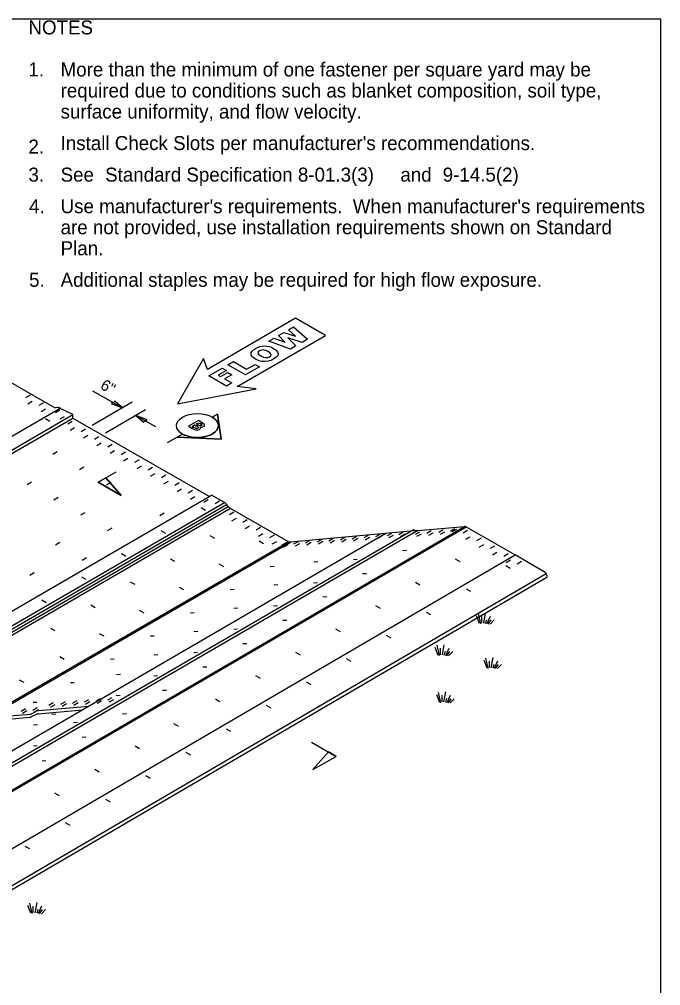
# Model space of a CAD drawing. Extents: x 99862 to 103151, y 100000 to 102076.
# Drawn here: x 102236 to 103151, y 100697 to 102076 of the extents above; entities that cross this region are included whole.
import ezdxf

# ---------------------------------------------------------------- set-up
doc = ezdxf.new("R2010")
doc.units = 0
for name, color, linetype in [('Level 1', 7, 'Continuous'), ('Level 15', 7, 'Continuous'), ('Level 20', 7, 'Continuous'), ('Level 25', 7, 'Continuous'), ('Level 31', 7, 'Continuous'), ('Level 32', 7, 'Continuous'), ('Level 33', 7, 'Continuous'), ('Level 34', 7, 'Continuous'), ('Level 36', 7, 'Continuous'), ('Level 60', 7, 'Continuous')]:
    doc.layers.add(name, color=color, linetype=linetype)

msp = doc.modelspace()

# ---------------------------------------------------------------- linework, layer by layer
at = {"layer": 'Level 1'}
msp.add_lwpolyline([(99862, 99999.5), (103151, 99999.5), (103151, 102075.5), (99862, 102075.5)], close=True, dxfattribs=at)
at = {"layer": 'Level 15'}
for p, q in [((102340.6, 101545.8), (102383.2, 101521.4)), ((102397.1, 101529.4), (102339.9, 101496.3)), ((102416.2, 101518.5), (102359, 101485.4)), ((102402.3, 101510.5), (102430.1, 101494.6))]:
    msp.add_line(p, q, dxfattribs=at)
for points in [[(102383.2, 101521.4), (102372.3, 101530.8), (102370.2, 101528.9), (102366.9, 101527.7)], [(102402.3, 101510.5), (102413.3, 101501.1), (102415.3, 101503), (102418.6, 101504.2)]]:
    msp.add_lwpolyline(points, close=True, dxfattribs=at)
at = {"layer": 'Level 20'}
for p, q in [((102447.5, 101471.9), (102468.8, 101484)), ((102348.6, 101415.4), (102374.4, 101430.2)), ((102653, 101044.5), (102688, 101024.3))]:
    msp.add_line(p, q, dxfattribs=at)
for points in [[(102547, 101551.7), (102673, 101624.4), (102630.2, 101649.1), (102504.3, 101576.3), (102498.9, 101591.7), (102461.5, 101527), (102573.7, 101548.6), (102547, 101551.7)], [(102630.4, 101609.7), (102622.8, 101605.3), (102592.1, 101616.6), (102599.5, 101620.9), (102614.9, 101615.2), (102605.8, 101624.5), (102613.6, 101629), (102629.8, 101623.8), (102619.9, 101632.7), (102627.1, 101636.8), (102646.9, 101619.2), (102639.3, 101614.8), (102619, 101621.4), (102630.4, 101609.7)], [(102586.5, 101587.4), (102581.9, 101587.7), (102579.6, 101588.1), (102577.3, 101588.8), (102575, 101589.8), (102572.8, 101590.9), (102570.1, 101592.7), (102568.2, 101594.6), (102567, 101596.5), (102566.6, 101598.5), (102567, 101600.4), (102568.2, 101602.3), (102570.1, 101604.2), (102572.8, 101606), (102575.9, 101607.6), (102579.2, 101608.7), (102582.5, 101609.4), (102585.8, 101609.6), (102589.2, 101609.4), (102592.5, 101608.8), (102595.6, 101607.7), (102598.7, 101606.1), (102602.4, 101603.6), (102604.5, 101601.1), (102605.2, 101598.6), (102604.6, 101596), (102602.6, 101593.5), (102599.2, 101591.1), (102594.9, 101589), (102590.8, 101587.8), (102586.5, 101587.4)], [(102587.5, 101593), (102590.5, 101593.3), (102593.1, 101594.3), (102595, 101595.8), (102595.4, 101597.5), (102594.1, 101599.4), (102590.9, 101601.7), (102587.4, 101603.3), (102584.1, 101603.9), (102581.2, 101603.7), (102578.5, 101602.6), (102576.8, 101601.1), (102576.4, 101599.5), (102577.6, 101597.5), (102580.6, 101595.4), (102584.2, 101593.7), (102587.5, 101593)], [(102539.1, 101557), (102531.4, 101552.5), (102506.2, 101567), (102525.6, 101578.2), (102531.4, 101574.8), (102519.8, 101568.1), (102523.1, 101566.2), (102533.3, 101572), (102539.1, 101568.7), (102528.9, 101562.8), (102539.1, 101557)], [(102578.7, 101579.8), (102558.9, 101568.4), (102533.7, 101582.9), (102541.4, 101587.4), (102560.3, 101576.5), (102572.4, 101583.4), (102578.7, 101579.8)]]:
    msp.add_lwpolyline(points, dxfattribs=at)
at = {"layer": 'Level 25'}
for p, q in [((102511.3, 101508.2), (102518.8, 101512.5)), ((102518.8, 101512.5), (102511.3, 101508.2)), ((102518.8, 101512.5), (102524.1, 101476.5)), ((102524.1, 101476.5), (102518.8, 101512.5)), ((102484.8, 101493.7), (102482.3, 101492.5)), ((102482.3, 101492.5), (102484.8, 101493.7)), ((102491.1, 101496.9), (102488.5, 101495.6)), ((102488.5, 101495.6), (102491.1, 101496.9)), ((102497.1, 101499.9), (102494.5, 101498.6)), ((102494.5, 101498.6), (102497.1, 101499.9)), ((102461.3, 101479.7), (102468.8, 101484)), ((102468.8, 101484), (102461.3, 101479.7)), ((102524.1, 101476.5), (102461.3, 101479.7)), ((102461.3, 101479.7), (102524.1, 101476.5))]:
    msp.add_line(p, q, dxfattribs=at)
for points in [[(102497.1, 101499.9), (102491.4, 101503.1), (102477.5, 101495.2), (102482.3, 101492.5)], [(102482.3, 101492.5), (102485.8, 101490.6), (102487, 101490.1), (102488.3, 101489.8), (102489.6, 101489.8), (102490.9, 101489.9), (102492.1, 101490.3), (102493.2, 101490.7), (102494.1, 101491.4), (102494.6, 101492.3), (102494.6, 101493.1), (102494.1, 101494), (102495.3, 101493.8), (102496.7, 101493.9), (102497.9, 101494.2), (102499, 101494.7), (102499.8, 101495.2), (102500.2, 101495.9), (102500.4, 101496.5), (102500.3, 101497.2), (102500, 101497.8), (102499.4, 101498.3), (102497.1, 101499.9)], [(102484.8, 101493.7), (102482.6, 101495), (102486.1, 101497), (102488.5, 101495.6), (102488.5, 101495.6)], [(102488.5, 101495.6), (102490.1, 101494.6), (102491, 101494), (102491.3, 101493.5), (102491.3, 101493.1), (102491.1, 101492.7), (102490.7, 101492.3), (102489.9, 101492), (102489.1, 101491.9), (102488.3, 101492), (102487.5, 101492.3), (102485.4, 101493.4), (102484.8, 101493.7)], [(102491.1, 101496.9), (102490.5, 101497.2), (102488.5, 101498.4), (102491.7, 101500.2), (102493.4, 101499.2), (102494.5, 101498.6)], [(102494.5, 101498.6), (102495.9, 101497.7), (102496.4, 101497.2), (102496.6, 101496.8), (102496.4, 101496.3), (102495.9, 101496), (102495.2, 101495.7), (102494.4, 101495.6), (102493.5, 101495.7), (102492.7, 101496), (102491.1, 101496.9)], [(102359.6, 101421.7), (102381.5, 101396.5), (102348.6, 101415.4), (102359.6, 101421.7)], [(102348.6, 101415.4), (102381.5, 101396.5), (102359.6, 101421.7), (102348.6, 101415.4)], [(102677.1, 101030.6), (102654.8, 101005.4), (102688, 101024.3), (102677.1, 101030.6)], [(102677.1, 101030.6), (102654.8, 101005.4), (102688, 101024.3), (102677.1, 101030.6)]]:
    msp.add_lwpolyline(points, dxfattribs=at)
msp.add_ellipse((102490.1, 101496.1), major_axis=(29.9, 0.1), ratio=0.572617, dxfattribs=at)
for start_param, end_param in [(3.920114, 7.061799), (5.490949, 7.061799), (3.920114, 5.425871), (5.425871, 5.490949)]:
    msp.add_ellipse((102490.1, 101496.1), major_axis=(29.9, 0.1), ratio=0.572617, start_param=start_param, end_param=end_param, dxfattribs=at)
at = {"layer": 'Level 31'}
for p, q in [((102892.7, 101213.7), (102888.4, 101224.7)), ((102894.3, 101213.4), (102891, 101228.1)), ((102896, 101214.6), (102896, 101223.8)), ((102898.6, 101214.3), (102901.3, 101228.8)), ((102901.3, 101214), (102902.9, 101219.5)), ((102903.3, 101213.6), (102908.1, 101224.1)), ((102904.9, 101213), (102909.1, 101218.9)), ((102907.6, 101213), (102913.5, 101219)), ((102833.7, 101168.4), (102829.3, 101179.4)), ((102835.3, 101168.1), (102832, 101182.8)), ((102837, 101169.3), (102837, 101178.5)), ((102839.6, 101169), (102842.3, 101183.5)), ((102844.3, 101168.3), (102849.1, 101178.8)), ((102842.3, 101168.8), (102843.9, 101174.2)), ((102845.9, 101167.7), (102850, 101173.7)), ((102848.5, 101167.7), (102854.5, 101173.7)), ((102904.9, 101149.8), (102901.6, 101164.5)), ((102909.2, 101150.7), (102911.9, 101165.2)), ((102903.3, 101150.1), (102899, 101161.1)), ((102906.6, 101151), (102906.6, 101160.2)), ((102911.9, 101150.4), (102913.5, 101155.9)), ((102913.9, 101150), (102918.7, 101160.5)), ((102915.5, 101149.4), (102919.7, 101155.3)), ((102918.2, 101149.4), (102924.1, 101155.4)), ((102835.8, 101101.2), (102831.5, 101112.2)), ((102837.4, 101100.9), (102834.1, 101115.6)), ((102839.1, 101102.2), (102839.1, 101111.4)), ((102841.8, 101101.9), (102844.5, 101116.4)), ((102846.5, 101101.1), (102851.3, 101111.7)), ((102844.5, 101101.6), (102846.1, 101107.1)), ((102848.1, 101100.6), (102852.2, 101106.5)), ((102850.7, 101100.6), (102856.6, 101106.6)), ((102252.6, 100800.6), (102248.3, 100811.6)), ((102254.2, 100800.3), (102250.9, 100815)), ((102255.9, 100801.5), (102255.9, 100810.7)), ((102258.6, 100801.2), (102261.3, 100815.7)), ((102261.3, 100801), (102262.9, 100806.4)), ((102263.3, 100800.5), (102268.1, 100811)), ((102264.9, 100799.9), (102269, 100805.9)), ((102267.5, 100799.9), (102273.4, 100805.9))]:
    msp.add_line(p, q, dxfattribs=at)
msp.add_lwpolyline([(102076.8, 100748.1), (102988.4, 101279.9)], dxfattribs=at)
at = {"layer": 'Level 32'}
msp.add_line((102312.5, 101506.6), (102507.3, 101395), dxfattribs=at)
at = {"layer": 'Level 33'}
for p, q in [((102758.7, 101342.1), (101851.6, 100814.7)), ((102799.4, 101348.1), (101885.5, 100817.3)), ((102804.5, 101346.3), (101890.1, 100815.2)), ((101954.5, 100818.6), (102871, 101352.2)), ((101957.1, 100818), (102873.6, 101351.6)), ((102986.2, 101286.5), (102943.4, 101311.7)), ((102988.4, 101282.7), (102988.4, 101279.9))]:
    msp.add_line(p, q, dxfattribs=at)
for points in [[(102804.5, 101346.3), (102871, 101352.2)], [(102873.6, 101351.6), (102943.4, 101311.7)], [(102030.9, 100779.4), (102943.4, 101311.7)], [(102075.3, 100752.6), (102987.8, 101284.9)]]:
    msp.add_lwpolyline(points, dxfattribs=at)
for centre, start, end in [((102871.4, 101347.7), 60.264, 95.0898), ((102983.9, 101282.7), 0, 59.4804)]:
    msp.add_arc(centre, 4.5, start, end, dxfattribs=at)
at = {"layer": 'Level 34'}
for p, q in [((102285.7, 101521.9), (102203.7, 101568.9)), ((102289.6, 101521.8), (102287.3, 101521.5)), ((102294.5, 101520.5), (101638.3, 101141.9)), ((101744.8, 101183.1), (102312.5, 101511.8)), ((102312.5, 101511.8), (102294.5, 101520.5)), ((102312.5, 101506.6), (102312.5, 101511.8)), ((101745.3, 101179), (102312.5, 101506.6)), ((102095.5, 101156.3), (102510.4, 101396.8)), ((102528.6, 101386.5), (102510.4, 101396.8)), ((102112.2, 101145.1), (102528.6, 101386.5)), ((102115.5, 101142.2), (102531.8, 101383.6)), ((102534.1, 101380.7), (102531.8, 101383.6)), ((102537.4, 101377.8), (102101.1, 101124.8)), ((102117.8, 101139.2), (102534.1, 101380.7)), ((102619.9, 101330.5), (102537.4, 101377.8)), ((102804.5, 101346.3), (102623.1, 101329.6)), ((102201.4, 101088.1), (102619.9, 101330.5)), ((102202.1, 101086.4), (102623.1, 101329.6)), ((102263.4, 101089.8), (102334.9, 101095.7)), ((102180.8, 101074), (102251.4, 101080)), ((102182.5, 101078.7), (102252, 101084.6)), ((102260.9, 101084.6), (102253.1, 101080.5)), ((102261.7, 101089.3), (102253.7, 101085.1)), ((102262.9, 101085.2), (102326.2, 101090.6))]:
    msp.add_line(p, q, dxfattribs=at)
for centre, start, end in [((102251, 101084.5), 274.8534, 297.6625), ((102251.6, 101089.1), 274.8534, 297.6625), ((102263.8, 101085.3), 94.8997, 117.6625)]:
    msp.add_arc(centre, 4.5, start, end, dxfattribs=at)
for centre, major_axis, ratio, start_param, end_param in [((102285.7, 101525.6), (2.23, -3.87), 0.581719, 5.498177, 6.032289), ((102294.5, 101509.6), (6.7, -11.6), 0.581714, 2.356435, 2.890593), ((102267.7, 101072.9), (-6.8, 11.7), 0.579285, 6.016164, 6.283108)]:
    msp.add_ellipse(centre, major_axis=major_axis, ratio=ratio, start_param=start_param, end_param=end_param, dxfattribs=at)
for points in [[(102531.8, 101383.6), (102530.8, 101384.8), (102529.7, 101385.8), (102528.6, 101386.5)], [(102537.4, 101377.8), (102536.2, 101378.4), (102535.1, 101379.4), (102534.1, 101380.7)], [(102623.1, 101329.6), (102622.1, 101329.5), (102621.1, 101329.8), (102619.9, 101330.5)]]:
    msp.add_open_spline(points, degree=3, dxfattribs=at)
at = {"layer": 'Level 36'}
for p, q in [((102251.3, 101539.4), (102245, 101535.8)), ((102251.3, 101539.4), (102245, 101535.8)), ((102254.5, 101530.3), (102248.2, 101526.7)), ((102270.3, 101528.5), (102264, 101524.9)), ((102273.5, 101519.4), (102267.2, 101515.8)), ((102294, 101518), (102287.7, 101514.4)), ((102300, 101508.8), (102293.7, 101505.1)), ((102273.2, 101506.1), (102279.6, 101502.5)), ((102311.5, 101501.9), (102305.2, 101498.3)), ((102311.5, 101501.9), (102305.2, 101498.3)), ((102311.5, 101501.9), (102305.2, 101498.3)), ((102314.7, 101492.8), (102308.4, 101489.2)), ((102314.7, 101492.8), (102308.4, 101489.2)), ((102330.6, 101491), (102324.3, 101487.3)), ((102330.6, 101491), (102324.3, 101487.3)), ((102333.8, 101481.9), (102327.5, 101478.2)), ((102333.8, 101481.9), (102327.5, 101478.2)), ((102349.6, 101480.1), (102343.3, 101476.4)), ((102349.6, 101480.1), (102343.3, 101476.4)), ((102352.8, 101471), (102346.5, 101467.3)), ((102352.8, 101471), (102346.5, 101467.3)), ((102368.7, 101469.1), (102362.4, 101465.5)), ((102368.7, 101469.1), (102362.4, 101465.5)), ((102290.1, 101458.7), (102283.8, 101455)), ((102371.9, 101460), (102365.6, 101456.4)), ((102371.9, 101460), (102365.6, 101456.4)), ((102387.7, 101458.2), (102381.4, 101454.6)), ((102387.7, 101458.2), (102381.4, 101454.6)), ((102387.7, 101458.2), (102381.4, 101454.6)), ((102391, 101449.1), (102384.7, 101445.5)), ((102391, 101449.1), (102384.7, 101445.5)), ((102406.8, 101447.3), (102400.5, 101443.6)), ((102410.1, 101438.2), (102403.8, 101434.5)), ((102328.2, 101436.8), (102321.9, 101433.2)), ((102425.9, 101436.4), (102419.6, 101432.7)), ((102429.1, 101427.2), (102422.8, 101423.6)), ((102445, 101425.4), (102438.7, 101421.8)), ((102253.4, 101415.4), (102247.1, 101411.8)), ((102366.4, 101415), (102360.1, 101411.3)), ((102448.2, 101416.3), (102441.9, 101412.7)), ((102464.1, 101414.5), (102457.8, 101410.8)), ((102467.3, 101405.4), (102461, 101401.7)), ((102483.2, 101403.5), (102476.9, 101399.9)), ((102291.5, 101393.6), (102285.2, 101389.9)), ((102486.4, 101394.4), (102480.1, 101390.8)), ((102505.6, 101390.1), (102499.3, 101386.4)), ((102521.5, 101388.3), (102515.2, 101384.6)), ((102329.7, 101371.7), (102323.4, 101368.1)), ((102442.7, 101371.2), (102436.4, 101367.6)), ((102501.8, 101375.2), (102495.4, 101378.8)), ((102524.7, 101379.1), (102518.4, 101375.5)), ((102542, 101372.6), (102535.7, 101368.9)), ((102545.2, 101363.4), (102538.9, 101359.8)), ((102561.1, 101361.6), (102554.8, 101358)), ((102561.1, 101361.6), (102554.8, 101358)), ((102367.8, 101349.8), (102361.5, 101346.2)), ((102445, 101342.3), (102438.6, 101345.9)), ((102445, 101342.3), (102438.6, 101345.9)), ((102564.4, 101352.5), (102558.1, 101348.8)), ((102580.2, 101350.6), (102573.9, 101347)), ((102583.5, 101341.5), (102577.2, 101337.8)), ((102767.2, 101342.4), (102760.9, 101338.8)), ((102783.8, 101343.9), (102777.5, 101340.2)), ((102807.1, 101344.3), (102800.8, 101340.6)), ((102823.8, 101345.8), (102817.5, 101342.1)), ((102823.8, 101345.8), (102817.5, 101342.1)), ((102825.9, 101342.8), (102819.6, 101339.2)), ((102840.6, 101347.3), (102834.3, 101343.6)), ((102842.7, 101344.3), (102836.4, 101340.7)), ((102857.4, 101348.8), (102851.1, 101345.1)), ((102859.5, 101348.1), (102853.2, 101344.5)), ((102875.4, 101346.3), (102869.1, 101342.6)), ((102293.8, 101329.2), (102287.5, 101325.6)), ((102514.7, 101335.1), (102508.3, 101338.7)), ((102584.3, 101327.4), (102578, 101331.1)), ((102599.4, 101339.7), (102593.1, 101336)), ((102602.7, 101330.5), (102596.4, 101326.9)), ((102617, 101329.1), (102610.7, 101325.4)), ((102633.7, 101330.5), (102627.4, 101326.9)), ((102650.4, 101332), (102644.1, 101328.4)), ((102652.4, 101329.1), (102646.1, 101325.4)), ((102667.1, 101333.5), (102660.8, 101329.9)), ((102667.1, 101333.5), (102660.8, 101329.9)), ((102669.1, 101330.6), (102662.8, 101326.9)), ((102683.7, 101335), (102677.4, 101331.3)), ((102685.8, 101332.1), (102679.5, 101328.4)), ((102700.4, 101336.5), (102694.1, 101332.8)), ((102702.5, 101333.6), (102696.2, 101329.9)), ((102717.1, 101338), (102710.8, 101334.3)), ((102719.1, 101335), (102712.8, 101331.4)), ((102733.8, 101339.5), (102727.5, 101335.8)), ((102733.8, 101339.5), (102727.5, 101335.8)), ((102735.8, 101336.5), (102729.5, 101332.9)), ((102750.5, 101340.9), (102744.2, 101337.3)), ((102752.5, 101338), (102746.2, 101334.4)), ((102769.2, 101339.5), (102762.9, 101335.8)), ((102785.9, 101341), (102779.6, 101337.3)), ((102809.1, 101341.3), (102802.8, 101337.7)), ((102878.8, 101337.1), (102872.5, 101333.5)), ((102894.7, 101335.3), (102888.4, 101331.6)), ((102619.1, 101326.1), (102612.8, 101322.5)), ((102635.7, 101327.6), (102629.4, 101324)), ((102782.7, 101318.1), (102788.3, 101318.5)), ((102898.1, 101326.1), (102891.7, 101322.4)), ((102914, 101324.3), (102907.7, 101320.6)), ((102917.4, 101315.1), (102911, 101311.4)), ((102332, 101307.3), (102325.7, 101303.7)), ((102388.2, 101309.3), (102381.8, 101313)), ((102388.2, 101309.3), (102381.8, 101313)), ((102457.9, 101302.2), (102451.6, 101305.8)), ((102656.1, 101301.9), (102661.7, 101302.3)), ((102712.6, 101305), (102718.2, 101305.4)), ((102858, 101305.9), (102864.4, 101302.2)), ((102933.3, 101313.2), (102927, 101309.6)), ((102936.7, 101304), (102930.4, 101300.4)), ((102952.6, 101302.2), (102946.3, 101298.5)), ((102527.6, 101294.6), (102521.2, 101298.2)), ((102593.8, 101295.3), (102599.4, 101295.7)), ((102930.1, 101296.5), (102936.5, 101292.8)), ((102257.1, 101285.9), (102250.8, 101282.3)), ((102331.3, 101276.4), (102325, 101280)), ((102331.3, 101276.4), (102325, 101280)), ((102401.1, 101269.2), (102394.8, 101272.9)), ((102725.8, 101284.9), (102731.4, 101285.3)), ((102801.1, 101272.8), (102807.5, 101269)), ((102470.8, 101261.6), (102464.4, 101265.3)), ((102536.9, 101262.3), (102542.5, 101262.6)), ((102599.2, 101268.8), (102604.8, 101269.2)), ((102655.8, 101272), (102661.4, 101272.4)), ((102873.3, 101263.4), (102879.7, 101259.7)), ((102274.4, 101243.3), (102268, 101247)), ((102668.9, 101251.7), (102674.5, 101252.1)), ((102344.3, 101236.3), (102337.9, 101239.9)), ((102413.9, 101228.6), (102407.5, 101232.3)), ((102542.2, 101235.6), (102547.8, 101236)), ((102598.8, 101238.9), (102604.5, 101239.3)), ((102744.1, 101239.6), (102750.6, 101235.8)), ((102480, 101229.1), (102485.6, 101229.5)), ((102611.9, 101218.5), (102617.5, 101218.8)), ((102816.4, 101230.2), (102822.8, 101226.5)), ((102287.3, 101203.3), (102280.9, 101206.9)), ((102541.9, 101205.7), (102547.5, 101206.1)), ((102687.1, 101206.3), (102693.6, 101202.6)), ((102357, 101195.6), (102350.6, 101199.3)), ((102423, 101196), (102428.6, 101196.4)), ((102485.1, 101202.5), (102490.7, 101202.8)), ((102759.4, 101197), (102765.9, 101193.3)), ((102554.8, 101185.2), (102560.4, 101185.5)), ((102300, 101162.6), (102293.6, 101166.2)), ((102366, 101162.8), (102371.5, 101163.2)), ((102428, 101169.2), (102433.6, 101169.6)), ((102484.8, 101172.5), (102490.4, 101172.9)), ((102630.1, 101173), (102636.5, 101169.3)), ((102702.4, 101163.7), (102708.9, 101160)), ((102497.7, 101151.8), (102503.3, 101152.2)), ((102374.7, 101141.1), (102380.3, 101141.5)), ((102427.7, 101139.3), (102433.3, 101139.7)), ((102572.9, 101139.7), (102579.4, 101136)), ((102242.9, 101129.5), (102236.5, 101133.2)), ((102308.8, 101129.6), (102314.4, 101129.9)), ((102645.4, 101130.5), (102651.8, 101126.8)), ((102368.1, 101108), (102361.8, 101104.4)), ((102374.4, 101111.2), (102380, 101111.6)), ((102440.5, 101118.5), (102446.1, 101118.8)), ((102261.5, 101093.6), (102255.2, 101089.9)), ((102255.6, 101101.5), (102261.2, 101101.8)), ((102284.5, 101100.6), (102278.2, 101096.9)), ((102286.5, 101097.7), (102280.2, 101094)), ((102301.2, 101102.1), (102294.9, 101098.4)), ((102303.2, 101099.1), (102296.9, 101095.5)), ((102317.9, 101103.6), (102311.6, 101099.9)), ((102320, 101100.6), (102313.7, 101097)), ((102334.6, 101105), (102328.3, 101101.4)), ((102336.7, 101102.1), (102330.4, 101098.5)), ((102351.4, 101106.5), (102345.1, 101102.9)), ((102353.4, 101103.6), (102347.1, 101099.9)), ((102370.2, 101105.1), (102363.9, 101101.4)), ((102515.7, 101106.3), (102522.2, 101102.6)), ((102588.2, 101097.1), (102594.7, 101093.4)), ((102244.8, 101092.1), (102238.5, 101088.4)), ((102246.9, 101089.2), (102240.6, 101085.5)), ((102263.6, 101090.7), (102257.3, 101087)), ((102282.5, 101084.6), (102288.1, 101085)), ((102383.2, 101085.1), (102388.8, 101085.4)), ((102256.3, 101069.3), (102261.9, 101069.7)), ((102313.3, 101072.7), (102318.9, 101073.1)), ((102456, 101071.3), (102462.5, 101067.6)), ((102325.9, 101051.6), (102331.4, 101052)), ((102531, 101063.8), (102537.5, 101060.1)), ((102256, 101039.4), (102261.6, 101039.8)), ((102401.1, 101039.5), (102407.6, 101035.7)), ((102473.7, 101030.4), (102480.2, 101026.7)), ((102268.5, 101018.1), (102274, 101018.5)), ((102343.7, 101006), (102350.1, 101002.3)), ((102416.4, 100996.9), (102422.9, 100993.2)), ((102286.2, 100972.5), (102292.7, 100968.7)), ((102359, 100963.5), (102365.4, 100959.7)), ((102301.5, 100929.9), (102308, 100926.2)), ((102244, 100896.4), (102250.4, 100892.7))]:
    msp.add_line(p, q, dxfattribs=at)
at = {"layer": 'Level 60'}
msp.add_line((103151, 102075.5), (103151, 102075.5), dxfattribs=at)

# ---------------------------------------------------------------- texts
at = {"layer": 'Level 20'}
for s, p in [('NOTES', (102249, 102054)), ('1.', (102249, 101994)), ('More than the minimum of one fastener per square yard may be', (102294.9, 101994)), ('required due to conditions such as blanket composition, soil type,', (102294.9, 101964)), ('surface uniformity, and flow velocity.', (102294.9, 101934)), ("Install Check Slots per manufacturer's recommendations.", (102294.9, 101889)), ('2.', (102249, 101884)), ('3.', (102249, 101844)), ('See ', (102294.9, 101844)), ('Standard Specification 8-01.3(3) ', (102358.4, 101844)), ('and ', (102779.6, 101844)), ('9-14.5(2)', (102840, 101844)), ('4.', (102249.9, 101799)), ("Use manufacturer's requirements.  When manufacturer's requirements", (102294.9, 101799)), ('are not provided, use installation requirements shown on Standard ', (102294.9, 101769)), ('Plan.', (102294.9, 101739)), ('5.', (102249.9, 101694)), ('Additional staples may be required for high flow exposure.', (102294.9, 101694))]:
    msp.add_text(s, height=20, dxfattribs=at).set_placement(p)
msp.add_text('6"', height=16, rotation=330.0271, dxfattribs=at).set_placement((102350.2, 101549.4))

doc.saveas('drawing.dxf')
